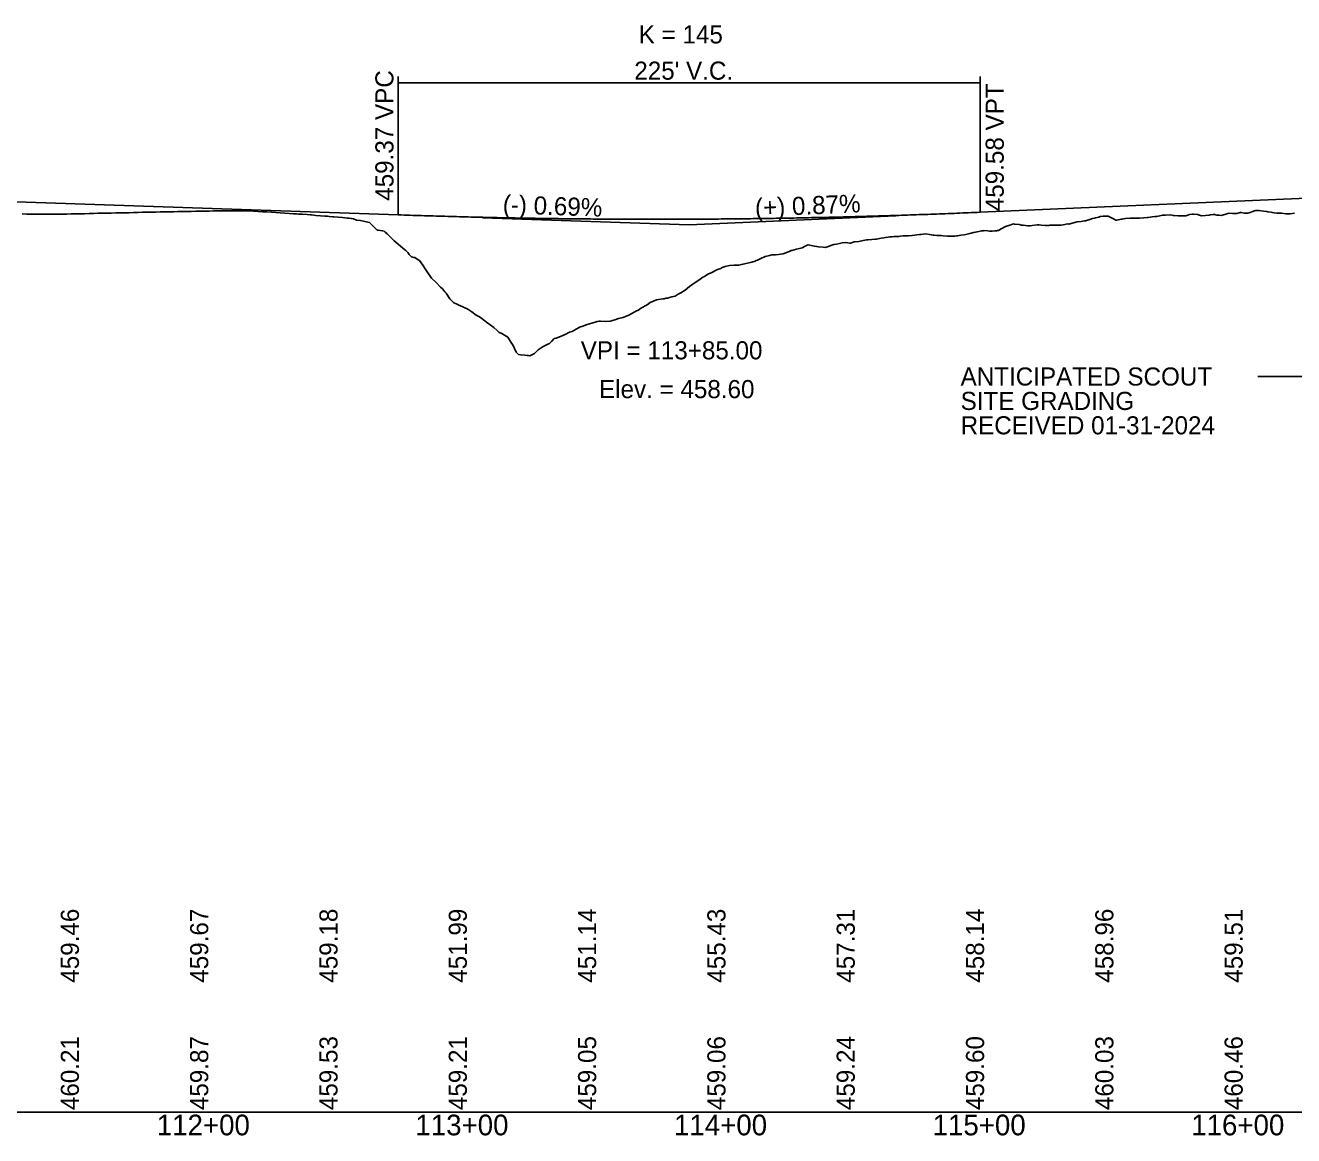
# Model space of a CAD drawing. Extents: x 2017200 to 2047700, y 854850 to 893350.
# Drawn here: x 2022628.3 to 2023118.7, y 862090.9 to 862520.1 of the extents above; entities that cross this region are included whole.
import ezdxf

# ---------------------------------------------------------------- set-up
doc = ezdxf.new("R2010")
doc.units = 0
for name, color, linetype in [('RD_DDB_GradeTX', 7, 'Continuous'), ('RD_DDB_Profile_Elev', 7, 'Continuous'), ('RD_DDB_Profile_EX', 7, 'Continuous'), ('RD_DDB_Profile_Lbl', 7, 'Continuous'), ('RD_DDB_Profile_PR', 7, 'Continuous'), ('RD_DDB_StaTX', 7, 'Continuous'), ('RD_DDB_StripGrade', 7, 'Continuous'), ('RD_DDB_VCLbl', 7, 'Continuous'), ('RD_GPK_Profile_Cell', 7, 'Continuous')]:
    doc.layers.add(name, color=color, linetype=linetype)

msp = doc.modelspace()

# ---------------------------------------------------------------- linework, layer by layer
at = {"layer": 'RD_DDB_GradeTX'}
for p in [(2022805.05, 862445.75), (2022964.92, 862446.47)]:
    msp.add_line(p, (2022885, 862443), dxfattribs=at)
at = {"layer": 'RD_DDB_Profile_Elev'}
msp.add_lwpolyline([(2023104.8, 862384.41), (2023130.4, 862384.41), (2023168.55, 862445)], dxfattribs=at)
at = {"layer": 'RD_DDB_Profile_EX'}
msp.add_lwpolyline([(2022627.09, 862447.22), (2022628.81, 862447.2), (2022630.53, 862447.19), (2022632.26, 862447.17), (2022632.96, 862447.17), (2022634.25, 862447.18), (2022635.7, 862447.17), (2022637.42, 862447.16), (2022639.14, 862447.16), (2022640.86, 862447.15), (2022642.86, 862447.14), (2022643.41, 862447.15), (2022644.3, 862447.18), (2022646.02, 862447.22), (2022647.19, 862447.25), (2022647.74, 862447.25), (2022648.98, 862447.25), (2022649.46, 862447.26), (2022651.18, 862447.31), (2022652.9, 862447.36), (2022654.62, 862447.41), (2022656.34, 862447.46), (2022656.98, 862447.48), (2022658.06, 862447.48), (2022659.34, 862447.48), (2022659.78, 862447.49), (2022661.5, 862447.54), (2022663.22, 862447.59), (2022664.94, 862447.64), (2022666.69, 862447.7), (2022668.38, 862447.7), (2022670.1, 862447.75), (2022671.82, 862447.8), (2022673.54, 862447.86), (2022674.63, 862447.89), (2022675.26, 862447.91), (2022676.98, 862447.94), (2022678.7, 862447.97), (2022680.42, 862447.99), (2022682.14, 862448.02), (2022683.86, 862448.06), (2022685.58, 862448.1), (2022687.3, 862448.12), (2022689.02, 862448.14), (2022690.18, 862448.16), (2022690.74, 862448.17), (2022692.46, 862448.22), (2022694.18, 862448.26), (2022695.38, 862448.29), (2022695.9, 862448.3), (2022697.62, 862448.33), (2022698.55, 862448.35), (2022699.34, 862448.35), (2022701.06, 862448.37), (2022702.78, 862448.38), (2022704.5, 862448.39), (2022706.23, 862448.41), (2022706.66, 862448.41), (2022707.97, 862448.44), (2022709.67, 862448.45), (2022711.39, 862448.46), (2022713.11, 862448.48), (2022713.78, 862448.48), (2022714.83, 862448.42), (2022716.55, 862448.31), (2022717.34, 862448.26), (2022718.27, 862448.21), (2022719.99, 862448.1), (2022721.71, 862447.98), (2022723.43, 862447.87), (2022725.15, 862447.76), (2022726.87, 862447.64), (2022728.59, 862447.54), (2022730.31, 862447.43), (2022732.03, 862447.32), (2022733.09, 862447.24), (2022733.88, 862447.19), (2022735.47, 862447.08), (2022737.19, 862446.96), (2022738.56, 862446.86), (2022738.91, 862446.83), (2022740.63, 862446.68), (2022742.35, 862446.54), (2022744.07, 862446.39), (2022745.1, 862446.3), (2022745.79, 862446.24), (2022747.17, 862446.14), (2022747.51, 862446.1), (2022749.23, 862445.95), (2022750.95, 862445.79), (2022752.67, 862445.63), (2022753.43, 862445.56), (2022754.39, 862445.4), (2022755.21, 862445.27), (2022756.39, 862444.77), (2022757.83, 862444.65), (2022759.55, 862444.29), (2022761.33, 862443.91), (2022762.99, 862442.29), (2022764.38, 862440.93), (2022764.71, 862440.89), (2022766.43, 862440.71), (2022766.97, 862440.58), (2022767.37, 862440.2), (2022768.15, 862439.47), (2022769.87, 862437.85), (2022770.89, 862436.88), (2022771.59, 862436.25), (2022773.31, 862434.77), (2022775.03, 862433.31), (2022775.44, 862433.03), (2022776.13, 862432.28), (2022776.75, 862431.56), (2022777.57, 862430.62), (2022778.48, 862430.44), (2022778.84, 862430.37), (2022780.2, 862429.52), (2022780.65, 862429.22), (2022781.92, 862427.37), (2022782.87, 862425.95), (2022783.64, 862424.8), (2022785.36, 862422.34), (2022787.08, 862420.68), (2022788.8, 862418.95), (2022789.52, 862418.21), (2022790.52, 862417.13), (2022791.06, 862416.54), (2022792.44, 862414.34), (2022793.96, 862412.85), (2022795.22, 862412.28), (2022795.68, 862412.07), (2022797.4, 862411.29), (2022798.17, 862410.93), (2022799.12, 862410.49), (2022799.42, 862410.35), (2022800.92, 862409.34), (2022802.56, 862408.1), (2022803.67, 862407.6), (2022804.28, 862407.15), (2022806, 862405.87), (2022806.63, 862405.4), (2022807.98, 862404.36), (2022809.44, 862403.29), (2022810.78, 862402.22), (2022811.16, 862401.82), (2022811.53, 862401.42), (2022812.33, 862401.07), (2022812.88, 862400.75), (2022814.89, 862399.57), (2022816.32, 862397.25), (2022816.74, 862396.56), (2022818.04, 862393.72), (2022818.95, 862392.92), (2022819.76, 862392.81), (2022821.48, 862392.58), (2022822.33, 862392.46), (2022822.81, 862392.45), (2022823.35, 862392.43), (2022825.1, 862393.26), (2022826.64, 862394.64), (2022827.02, 862394.97), (2022828.53, 862395.99), (2022830.33, 862396.82), (2022830.94, 862397.13), (2022831.8, 862398.02), (2022832.79, 862399.03), (2022833.52, 862399.25), (2022835.24, 862399.83), (2022836.96, 862400.64), (2022838.75, 862401.48), (2022839.72, 862401.83), (2022840.4, 862402.2), (2022842.12, 862403.14), (2022842.6, 862403.4), (2022843.84, 862403.82), (2022844.53, 862404.05), (2022845.56, 862404.46), (2022846.42, 862404.79), (2022847.28, 862405.02), (2022849, 862405.49), (2022849.42, 862405.6), (2022850.21, 862405.74), (2022850.73, 862405.73), (2022852.71, 862405.68), (2022854.39, 862405.71), (2022855.89, 862406.19), (2022857.7, 862406.77), (2022859.45, 862407.16), (2022860.59, 862407.7), (2022861.05, 862407.87), (2022861.41, 862408.01), (2022862.77, 862408.78), (2022864.62, 862409.74), (2022865.09, 862409.88), (2022866.21, 862410.63), (2022867.93, 862411.65), (2022868.74, 862412.13), (2022869.88, 862413), (2022871.37, 862413.61), (2022872.37, 862414.03), (2022873.09, 862414.13), (2022874.81, 862414.37), (2022875.26, 862414.43), (2022875.97, 862414.6), (2022876.53, 862414.72), (2022877.34, 862414.89), (2022878.25, 862415.12), (2022879.56, 862415.45), (2022879.97, 862415.73), (2022880.76, 862416.26), (2022881.69, 862416.77), (2022883.41, 862417.8), (2022885.13, 862419.12), (2022886.85, 862420.47), (2022888.73, 862421.67), (2022890.29, 862422.74), (2022890.92, 862422.98), (2022892.16, 862423.92), (2022893.73, 862424.63), (2022895.45, 862425.53), (2022895.86, 862425.74), (2022897.17, 862426.17), (2022897.49, 862426.36), (2022898.08, 862426.62), (2022898.89, 862426.84), (2022900.61, 862427.31), (2022902.33, 862427.38), (2022904.17, 862427.46), (2022905.77, 862427.79), (2022907.49, 862428.15), (2022909.21, 862428.63), (2022910.45, 862428.98), (2022910.93, 862429.21), (2022911.37, 862429.39), (2022912.65, 862429.98), (2022914.37, 862430.75), (2022916.09, 862431.16), (2022916.94, 862431.36), (2022917.81, 862431.42), (2022918.38, 862431.47), (2022919.53, 862431.58), (2022921.25, 862431.82), (2022922.98, 862432.47), (2022923.65, 862432.73), (2022924.35, 862433.04), (2022924.7, 862433.13), (2022926.42, 862433.56), (2022927.68, 862433.9), (2022928.14, 862433.99), (2022928.62, 862434.07), (2022929.86, 862434.76), (2022930.62, 862435.19), (2022930.99, 862435.26), (2022931.58, 862435.16), (2022933.3, 862434.82), (2022934.29, 862434.62), (2022935.02, 862434.54), (2022936.74, 862434.36), (2022937.58, 862434.27), (2022937.89, 862434.33), (2022938.46, 862434.53), (2022940.18, 862435.12), (2022940.86, 862435.35), (2022941.9, 862435.56), (2022943.12, 862435.81), (2022943.62, 862435.91), (2022944.12, 862436), (2022945.49, 862436.12), (2022947.06, 862435.95), (2022947.37, 862435.91), (2022948.78, 862436.44), (2022950.61, 862436.6), (2022952.22, 862436.92), (2022953.49, 862437.16), (2022954.06, 862437.22), (2022955.66, 862437.33), (2022957.05, 862437.42), (2022957.38, 862437.49), (2022959.26, 862437.92), (2022960.26, 862438.02), (2022960.82, 862438.11), (2022961.96, 862438.28), (2022962.54, 862438.33), (2022963.05, 862438.36), (2022963.45, 862438.41), (2022964.26, 862438.44), (2022965.4, 862438.48), (2022965.98, 862438.55), (2022966.64, 862438.63), (2022967.75, 862438.82), (2022969.42, 862438.82), (2022969.81, 862438.82), (2022971.14, 862438.89), (2022972.98, 862439.14), (2022973.98, 862439.24), (2022974.58, 862439.33), (2022976.3, 862439.54), (2022978.02, 862439.22), (2022978.64, 862439.11), (2022979.29, 862439.04), (2022979.74, 862439), (2022980.71, 862438.91), (2022981.46, 862438.88), (2022982.43, 862438.83), (2022983.19, 862438.76), (2022984.9, 862438.67), (2022985.56, 862438.64), (2022986.62, 862438.65), (2022987.63, 862438.67), (2022988.34, 862438.72), (2022988.69, 862438.75), (2022990.06, 862438.97), (2022991.34, 862439.18), (2022991.98, 862439.32), (2022993.5, 862439.71), (2022994.92, 862440.07), (2022995.22, 862440.11), (2022996.24, 862440.26), (2022996.95, 862440.4), (2022998.02, 862440.63), (2022998.67, 862440.72), (2022999.06, 862440.77), (2023000.39, 862440.67), (2023001.12, 862440.62), (2023002.11, 862440.62), (2023003.2, 862440.63), (2023003.83, 862440.73), (2023004.21, 862440.79), (2023004.53, 862440.86), (2023005.55, 862441.43), (2023007.29, 862442.39), (2023008.56, 862442.76), (2023008.99, 862442.9), (2023010.37, 862443.34), (2023010.71, 862443.3), (2023012.52, 862443.08), (2023013.44, 862442.89), (2023014.15, 862442.83), (2023015.87, 862442.69), (2023016.51, 862442.66), (2023016.87, 862442.69), (2023017.59, 862442.77), (2023019.57, 862443), (2023020.25, 862443.01), (2023021.03, 862442.93), (2023022.75, 862442.77), (2023024.02, 862442.78), (2023024.47, 862442.82), (2023025.68, 862442.93), (2023026.19, 862442.92), (2023027.91, 862442.88), (2023028.72, 862442.86), (2023029.63, 862443.03), (2023031.41, 862443.37), (2023031.77, 862443.31), (2023033.07, 862443.69), (2023033.59, 862443.84), (2023035.03, 862444.15), (2023036.51, 862444.34), (2023037.84, 862444.51), (2023038.23, 862444.62), (2023038.6, 862444.71), (2023039.95, 862445.12), (2023040.87, 862445.4), (2023041.67, 862445.58), (2023042.13, 862445.68), (2023043.39, 862446.03), (2023043.9, 862446.18), (2023045.11, 862446.33), (2023045.61, 862446.4), (2023046.92, 862446.36), (2023048.55, 862445.53), (2023049.05, 862445.28), (2023049.94, 862444.77), (2023050.27, 862444.83), (2023051.99, 862445.16), (2023052.45, 862445.25), (2023052.96, 862445.33), (2023053.71, 862445.4), (2023055.43, 862445.56), (2023056.11, 862445.64), (2023057.15, 862445.63), (2023057.53, 862445.62), (2023059.14, 862445.64), (2023060.59, 862445.77), (2023062, 862445.88), (2023062.43, 862445.9), (2023064.03, 862446.1), (2023065.01, 862446.22), (2023065.75, 862446.28), (2023067.47, 862446.64), (2023068.02, 862446.76), (2023069.2, 862446.8), (2023071.03, 862446.92), (2023072.1, 862446.64), (2023072.64, 862446.58), (2023074.03, 862446.43), (2023074.36, 862446.44), (2023075.27, 862446.47), (2023076.08, 862446.49), (2023077.04, 862446.52), (2023077.8, 862446.78), (2023078.4, 862446.98), (2023079.52, 862447.13), (2023080.04, 862447.2), (2023081.5, 862446.98), (2023083.04, 862446.45), (2023084.68, 862446.6), (2023086.04, 862446.81), (2023086.4, 862446.86), (2023087.63, 862447.05), (2023088.12, 862446.96), (2023089.04, 862446.77), (2023089.84, 862446.7), (2023090.66, 862446.62), (2023091.56, 862446.9), (2023092.04, 862447.06), (2023093.28, 862447.37), (2023093.66, 862447.46), (2023095.04, 862447.44), (2023096.72, 862447.45), (2023098.04, 862447.78), (2023098.44, 862447.72), (2023099.59, 862447.55), (2023100.16, 862447.54), (2023101.05, 862447.52), (2023101.88, 862447.84), (2023102.52, 862448.09), (2023103.6, 862448.43), (2023104.05, 862448.57), (2023105.43, 862448.53), (2023107.05, 862448.3), (2023108.32, 862448.11), (2023108.76, 862448.05), (2023110.05, 862447.87), (2023110.48, 862447.77), (2023111.18, 862447.62), (2023112.2, 862447.55), (2023113.06, 862447.5), (2023114.03, 862447.58), (2023115.64, 862447.3), (2023116.06, 862447.22), (2023116.86, 862447.24), (2023117.36, 862447.29), (2023119.08, 862447.47)], dxfattribs=at)
at = {"layer": 'RD_DDB_Profile_PR'}
for p, q in [((2022425, 862458.8), (2022772.5, 862446.86)), ((2022997.5, 862447.88), (2023250, 862458.83))]:
    msp.add_line(p, q, dxfattribs=at)
msp.add_spline([(2022772.5, 862446.86), (2022777, 862446.71), (2022781.5, 862446.57), (2022786, 862446.43), (2022790.5, 862446.3), (2022795, 862446.18), (2022799.5, 862446.06), (2022804, 862445.95), (2022808.5, 862445.85), (2022813, 862445.76), (2022817.5, 862445.67), (2022822, 862445.59), (2022826.5, 862445.51), (2022831, 862445.45), (2022835.5, 862445.39), (2022840, 862445.33), (2022844.5, 862445.29), (2022849, 862445.25), (2022853.5, 862445.22), (2022858, 862445.19), (2022862.5, 862445.17), (2022867, 862445.16), (2022871.5, 862445.16), (2022876, 862445.16), (2022880.5, 862445.17), (2022885, 862445.19), (2022889.5, 862445.21), (2022894, 862445.24), (2022898.5, 862445.28), (2022903, 862445.32), (2022907.5, 862445.37), (2022912, 862445.43), (2022916.5, 862445.5), (2022921, 862445.57), (2022925.5, 862445.65), (2022930, 862445.74), (2022934.5, 862445.83), (2022939, 862445.93), (2022943.5, 862446.04), (2022948, 862446.16), (2022952.5, 862446.28), (2022957, 862446.41), (2022961.5, 862446.54), (2022966, 862446.68), (2022970.5, 862446.83), (2022975, 862446.99), (2022979.5, 862447.15), (2022984, 862447.32), (2022988.5, 862447.5), (2022993, 862447.69), (2022997.5, 862447.88)], degree=3, dxfattribs=at)
at = {"layer": 'RD_DDB_VCLbl'}
for p, q in [((2022772.5, 862500.38), (2022772.5, 862446.86)), ((2022772.5, 862497.88), (2022997.5, 862497.88)), ((2022997.5, 862500.38), (2022997.5, 862447.88))]:
    msp.add_line(p, q, dxfattribs=at)
at = {"layer": 'RD_GPK_Profile_Cell'}
msp.add_line((2020500, 862100), (2024800, 862100), dxfattribs=at)

# ---------------------------------------------------------------- texts
at = {"layer": 'RD_DDB_GradeTX'}
for s, rotation, p in [('(-) 0.69%', 358.0324, (2022812.79, 862447.48)), ('(+) 0.87%', 2.483, (2022910.56, 862446.11))]:
    msp.add_text(s, height=7, rotation=rotation, dxfattribs=at).set_placement(p)
at = {"layer": 'RD_DDB_Profile_Elev'}
for s, p in [('ANTICIPATED SCOUT', (2022989.93, 862380.87)), ('SITE GRADING', (2022989.93, 862371.44)), ('RECEIVED 01-31-2024', (2022989.93, 862362.01))]:
    msp.add_text(s, height=7, dxfattribs=at).set_placement(p)
at = {"layer": 'RD_DDB_Profile_Lbl'}
for s, p in [('VPI = 113+85.00', (2022843.04, 862391)), ('Elev. = 458.60', (2022850.11, 862376))]:
    msp.add_text(s, height=7, dxfattribs=at).set_placement(p)
at = {"layer": 'RD_DDB_StaTX'}
for s, p in [('112+00', (2022679.1, 862091)), ('113+00', (2022779.1, 862091)), ('114+00', (2022879.1, 862091)), ('115+00', (2022979.1, 862091)), ('116+00', (2023079.1, 862091))]:
    msp.add_text(s, height=8, dxfattribs=at).set_placement(p)
at = {"layer": 'RD_DDB_StripGrade'}
for s, p in [('459.37 VPC', (2022770.62, 862452.31)), ('459.58 VPT', (2023006.61, 862448.28)), ('459.46', (2022649, 862150)), ('459.67', (2022699, 862150)), ('459.18', (2022749, 862150)), ('451.99', (2022799, 862150)), ('451.14', (2022849, 862150)), ('455.43', (2022899, 862150)), ('457.31', (2022949, 862150)), ('458.14', (2022999, 862150)), ('458.96', (2023049, 862150)), ('459.51', (2023099, 862150)), ('460.21', (2022649, 862100.75)), ('459.87', (2022699, 862100.75)), ('459.53', (2022749, 862100.75)), ('459.21', (2022799, 862100.75)), ('459.05', (2022849, 862100.75)), ('459.06', (2022899, 862100.75)), ('459.24', (2022949, 862100.75)), ('459.60', (2022999, 862100.75)), ('460.03', (2023049, 862100.75)), ('460.46', (2023099, 862100.75))]:
    msp.add_text(s, height=7, rotation=90, dxfattribs=at).set_placement(p)
at = {"layer": 'RD_DDB_VCLbl'}
for s, p in [('K = 145', (2022865.48, 862513.13)), ("225' V.C.", (2022863.75, 862499.13))]:
    msp.add_text(s, height=7, dxfattribs=at).set_placement(p)

doc.saveas('drawing.dxf')
